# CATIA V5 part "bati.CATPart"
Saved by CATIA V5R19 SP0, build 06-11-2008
Part number: Pièce6
Bounding box of the stored display mesh (mm): x -100 to 0, y -104.614 to 130.043, z -534.05 to 315.261
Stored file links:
  G:\EU_thinkMotion\CFAO_2010\SIL_groupe1\SIL_groupe1\A reprendre\lalpha\lalpha\Alpha.mécanisme\bati.CATPart
  G:\EU_thinkMotion\CFAO_2010\SIL_groupe1\SIL_groupe1\A reprendre\lalpha\lalpha\Alpha.mécanisme\Mecanisme_final.CATProduct
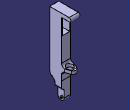
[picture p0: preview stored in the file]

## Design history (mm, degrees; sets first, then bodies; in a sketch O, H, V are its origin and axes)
Body1 (main body)
  Sketch1 on yz-plane, origin (0, 0, 0), H (0, 1, 0), V (0, 0, 1)
    line L1 (25.2317, 275.6492) -> (25.2317, -157.7613)
    line L2 (-104.6143, -280.8288) -> (-104.6143, 315.2607)
    line L3 (59.7592, -227.1702) -> (111.9383, -227.1702)
    line L4 (111.9383, -227.1702) -> (111.9383, -193.1842)
    line L5 (111.9383, -193.1842) -> (60.6546, -193.1842)
    line L6 (-104.6143, 315.2607) -> (107.72, 315.2607)
    line L7 (107.72, 275.6492) -> (25.2317, 275.6492)
    arc A1 centre (107.72, 295.455) radius 19.8057 from (107.72, 275.6492) to (107.72, 315.2607) ccw
    line L8 (25.2317, -323.6892) -> (25.2317, -499.3575)
    line L9 (-44.5358, -499.3575) -> (-44.5358, -379.9646)
    point P9 (-44.5358, -499.3575)
    arc A2 centre (-9.6521, -499.3575) radius 34.8838 from (-44.5358, -499.3575) to (25.2317, -499.3575) ccw
    point P11 (0, -532.8794)
    point P12 (-44.5358, -499.3575)
    point P13 (25.2317, -227.1702)
    line L10 (25.2317, -261.6977) -> (25.2317, -323.6892)
    arc A3 centre (59.7592, -261.6977) radius 34.5275 from (59.7592, -227.1702) to (25.2317, -261.6977) ccw
    arc A4 centre (60.6546, -157.7613) radius 35.4229 from (60.6546, -193.1842) to (25.2317, -157.7613) cw
    arc A5 centre (-100.8112, -379.9646) radius 56.2754 from (-74.7683, -330.0779) to (-44.5358, -379.9646) cw
    arc A6 centre (-49.0583, -280.8288) radius 55.556 from (-74.7683, -330.0779) to (-104.6143, -280.8288) cw
    radius A3 = 34.5275
    radius A4 = 35.4229
    radius A5 = 56.2754
    radius A6 = 55.556
    vertical: L1 V, L2 V, L4 V, L8 V, L10 V
    horizontal: L3 H, L5 H, L6 H, L7 H
    tangency: A1 L7, A2 L1, A3 L3, A3 L10, A4 L5, A4 L1, A5 L9, A6 L2, A6 A5
    parallelism: L8 L9
    coincidence: A2 P9, A2 P11, P11 V, L1 P13, L1 L10, L3 P13, L10 P13, P9 P12
  Pad1: profile Sketch1, direction (-1, 0, 0), length 100
  Sketch2 on face of Pad1 from Sketch1.L3, origin (0, 0, -227.1702), H (1, 0, 0), V (0, -1, 0)
    line L1 (-100.0503, -59.6488) -> (-80.1484, -111.9972)
    line L2 (-100.0503, -59.6488) -> (-100.0503, -111.9972)
    line L3 (-80.1484, -111.9972) -> (-100.0503, -111.9972)
    vertical: L2 V
    horizontal: L3 H
  Pocket1: profile Sketch2, direction (0, 0, 1), length 100
  Sketch3 on face of Pad1 from Sketch1.L3, origin (0, 0, -227.1702), H (1, 0, 0), V (0, -1, 0)
    line L1 (0, -60.1505) -> (-20.1082, -111.9972)
    point P1 (0, -60.1505)
    line L2 (0, -111.9972) -> (-20.1082, -111.9972)
    point P3 (0, -111.9972)
    line L3 (0, -60.1505) -> (0, -111.9972)
    coincidence: P1 V, P3 V
    horizontal: L2 H
    vertical: L3 V
  Pocket2: profile Sketch3, direction (0, 0, 1), length 100
  Sketch4 on face of Pad1 from Sketch1.L3, origin (0, 0, -227.1702), H (1, 0, 0), V (0, -1, 0)
    line L1 (-80.4283, -111.8356) -> (-20.1842, -111.8356)
    arc A1 centre (-50.3063, -96.3228) radius 33.8819 from (-80.4283, -111.8356) to (-20.1842, -111.8356) ccw
    horizontal: L1 H
  Pad2: profile Sketch4, direction (0, 0, 1), length 34
  Sketch5 on face of Pad1 from Sketch1.L8, origin (0, 25.2317, 0), H (-1, 0, 0), V (0, 0, 1)
    point P1 (0, -410.6699)
    line L1 (17.7734, -410.6699) -> (13.3738, -410.6699)
    line L2 (30.0304, -551.2435) -> (30.0304, -427.3265)
    line L3 (0, -410.6699) -> (0, -551.2435)
    line L4 (0, -551.2435) -> (30.0304, -551.2435)
    arc A1 centre (17.7734, -392.8964) radius 17.7734 from (0, -392.8964) to (17.7734, -410.6699) ccw
    line L5 (0, -410.6699) -> (0, -392.8964)
    arc A2 centre (13.3738, -427.3265) radius 16.6566 from (13.3738, -410.6699) to (30.0304, -427.3265) cw
    radius A1 = 17.7734
    radius A2 = 16.6566
    horizontal: L1 H, L4 H
    vertical: L2 V, L3 V
    coincidence: L1 P1
    tangency: A1 L1, L5 A1, A2 L1, A2 L2
  Pocket3: profile Sketch5, direction (0, -1, 0), length 80
  Sketch6 on face of Pocket3 from Sketch5.L2, origin (-30.0304, 0, 0), H (0, 1, 0), V (0, 0, 1)
    circle A1 centre (0, -500.1453) radius 12.5
    point P1 (0, -500.1453)
    coincidence: P1 V
  Pad3: profile Sketch6, direction (1, 0, 0), length 10
  Sketch7 on face of Pocket3 from Sketch5.L2, origin (-30.0304, 0, 0), H (0, 1, 0), V (0, 0, 1)
    circle A1 centre (0, -499.9727) radius 5
    point P1 (0, -499.9727)
    coincidence: P1 V
  Pocket4: profile Sketch7, direction (1, 0, 0), length 10
  Sketch8 on face of Pad1 from Sketch1.L1, origin (0, 25.2317, 0), H (-1, 0, 0), V (0, 0, 1)
    line L1 (9.7163, 275.6955) -> (90.2281, 275.6955)
    line L2 (90.2281, 275.6955) -> (90.2281, 98.7595)
    line L3 (90.2281, 98.7595) -> (9.7163, 98.7595)
    line L4 (9.7163, 98.7595) -> (9.7163, 275.6955)
    horizontal: L1 H, L3 H
    vertical: L2 V, L4 V
  Pocket5: profile Sketch8, direction (0, -1, 0), length 90
  Sketch9 on face of Pad1 from Sketch1.L7, origin (0, 0, 275.6492), H (1, 0, 0), V (0, -1, 0)
    circle A1 centre (-49.8994, -66.2086) radius 35
  Pocket6: profile Sketch9, direction (0, 0, 1), length 20
  Sketch10 on face of Pad1 from Sketch1.L6, origin (0, 0, 315.2607), H (1, 0, 0), V (0, 1, 0)
    point P1 (-49.9739, 66.8396)
  Sketch11 on face of Pad1 from Sketch1.L5, origin (0, 0, -193.1842), H (1, 0, 0), V (0, 1, 0)
    circle A1 centre (-49.9751, 66.8386) radius 34.5
  Pocket7: profile Sketch11, direction (0, 0, -1), length 27, opposite side length 30
  Sketch12 on end face of Pocket7, origin (0, 0, -220.1842), H (1, 0, 0), V (0, 1, 0)
    point P1 (-49.9639, 66.8581)
  Line1: stored without definition
  Line2: type PtDir, RefPoint Sketch12, Direction Line1, Start -566, End 20
  Sketch13 on face of Pad1 from Sketch1.L6, origin (0, 0, 315.2607), H (1, 0, 0), V (0, 1, 0)
    line L1 (-49.9827, 107.4178) -> (-49.9827, -105.7529)
    vertical: L1 V
  Sketch14 on face of Pad1 from Sketch1.L6, origin (0, 0, 315.2607), H (1, 0, 0), V (0, 1, 0)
